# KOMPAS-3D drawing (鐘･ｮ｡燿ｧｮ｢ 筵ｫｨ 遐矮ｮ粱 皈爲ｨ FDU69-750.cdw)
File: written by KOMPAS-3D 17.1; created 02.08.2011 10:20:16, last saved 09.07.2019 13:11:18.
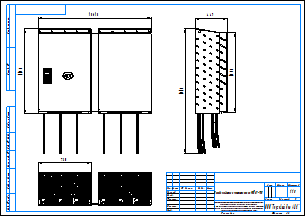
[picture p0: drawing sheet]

Title block, sheet 1: name: Преобразователи частоты серии FDU69-750; scale: 1:10; sheets: 1; sheet format: A3; stored path: \\adlc.lan\data\АДЛ_ПКД\3D-модели\Поставщики\Оборудование Emotron\Преобразователи частоты\Серия FDU 2.0\KOMPAS 2D\Преобразователи частоты серии FDU69-750.cdw

Views: Спереди 1
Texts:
  Рама для чертежей
  Лит-Масса-Масштаб
  Материал-Предприятие
  Масштаб
  Изм.
  Лист
  № докум.
  Подп.
  Дата
  Лит.
  Разраб.
  Пров.
  Т.контр.
  Листов
  Внимание! Данный продукт является объектом авторского права ООО «Торговый Дом АДЛ».
  Запрещается изменение, копирование, распространение
  (в том числе путем копирования на другие сайты и ресурсы в Интернете)
  или любое иное использование информации и объектов без предварительного
  согласия правообладателя (ООО «Торговый Дом АДЛ»).
  Н.контр.
  Утв.
  ООО "Торговый дом АДЛ"
  Изменение
  Номер документа
  Подпись
  Обозначение документа
  Наименование изделия
  Масса изделия по ГОСТ 2.109-73
  Порядковый номер листа
  Общее количество листов в документе
  Характер работы, выполненной лицом, подписавшим документ
  Наименование или индекс предприятия, выпускающего документ
  Инв. № подл.
  Подп. и дата
  Взам. инв. №
  Инв. № дубл.
  Инвентарный номер подлинника по ГОСТ 2.501-68
  Подпись принявшего подлинник в отдел технической документации
  Инвентарный номер подлинника, взамен которого выпущен данный подлинник
  Инвентарный номер дубликата по ГОСТ 2.502-68
  Подпись принявшего дубликат в отдел технической документации
  Справ. №
  Перв. примен.
  Обозначение документа, взамен или на основании которого выпущен данный документ
  Обозначение документа, в котором впервые записан данный документ
  Подпись лица, копировавшего чертеж
  Обозначение формата листа
  !Рама для чертежа
Dimensions and other numbers on the sheet: 1561,5; 1176; 730; 1718; 1096; 449; 1:10; 1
